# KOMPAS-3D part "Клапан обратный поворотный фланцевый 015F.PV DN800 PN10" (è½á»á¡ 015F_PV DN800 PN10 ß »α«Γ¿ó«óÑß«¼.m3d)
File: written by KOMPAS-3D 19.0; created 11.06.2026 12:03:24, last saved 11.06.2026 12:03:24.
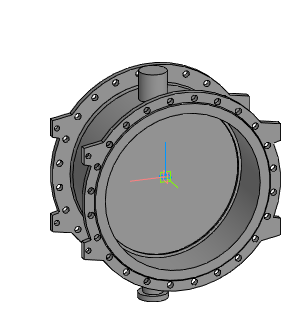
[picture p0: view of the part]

Document properties: Автор: Энергия; Полное имя файла: Z:\3.Личные\kachalov\001_3d для проектировщиков\5.5 Тип 015F.PV Клапан обратный поворотный с двумя эксцентриками\_stp_Клапан 015F.PV DN300-DN1200 с противовесом\Клапан 015F_PV DN800 PN10 с противовесом.m3d

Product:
- Part/product: Клапан обратный поворотный фланцевый 015F.PV DN800 PN10

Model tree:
1. Операция без истории:1
2. Сплайн:1
     Координата Y = 30; Координата Z = 400; Вес = 1; Координата X = 800; Координата Y = 135.322; Координата Z = 400; Вес = 0.333333; Координата X = 800; Координата Y = 135.322; Координата Z = -400; Вес = 0.333333; Координата Y = 30; Координата Z = -400; Вес = 1; Координата X = -800; Координата Y = -75.322; Координата Z = -400; Вес = 0.333333; Координата X = -800; Координата Y = -75.322; Координата Z = 400; Вес = 0.333333; Порядок = 4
